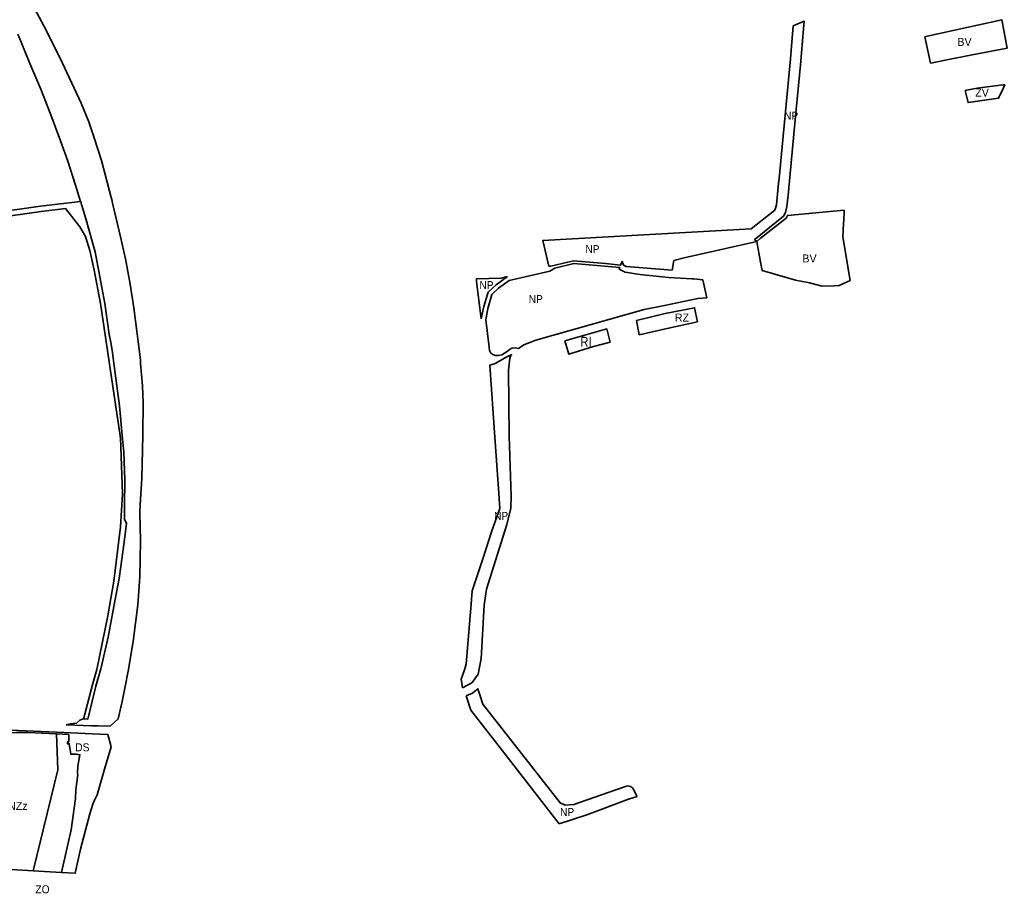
# Model space of a CAD drawing. Extents: x -650971 to -642489, y -1074311 to -1062745.
# Drawn here: x -645155 to -643674, y -1071023 to -1069701 of the extents above; entities that cross this region are included whole.
import ezdxf

# ---------------------------------------------------------------- set-up
doc = ezdxf.new("R2010")
doc.units = 0
doc.header["$LTSCALE"] = 4.8
for name, color, linetype, lineweight in [('15', 7, 'Continuous', 35), ('24', 7, 'Continuous', 35), ('3', 7, 'Continuous', 35), ('40', 7, 'Continuous', 35), ('42', 7, 'Continuous', 35), ('46', 7, 'Continuous', 35), ('48', 7, 'Continuous', 35), ('5', 7, 'Continuous', 35), ('6', 7, 'Continuous', 35), ('62', 7, 'Continuous', 35)]:
    doc.layers.add(name, color=color, linetype=linetype, lineweight=lineweight)

msp = doc.modelspace()

# ---------------------------------------------------------------- linework, layer by layer
at = {"layer": '15'}
for points in [[(-645469.701, -1069990.011), (-645453.852, -1069992.968), (-645350.784, -1070005.227), (-645222.809, -1069993.701), (-645195.011, -1069990.48), (-645124.233, -1069980.695), (-645064.052, -1069973.429)], [(-645064.052, -1069973.429), (-645063.96, -1069973.73), (-645063.23, -1069976.2), (-645062.57, -1069978.46), (-645061.76, -1069981.21), (-645054.73, -1070004.56), (-645047.28, -1070031.83), (-645042.27, -1070049.23), (-645032.21, -1070102.73), (-645027.49, -1070126.56), (-645021.14, -1070173.07), (-645018.56, -1070184.92), (-645016.92, -1070196.32), (-645013.77, -1070220.04), (-645005.98, -1070280.14), (-645001.81, -1070324.58), (-644999.47, -1070349.63), (-644997.87, -1070391.16), (-644998.25, -1070430.5), (-644998.17, -1070450.59), (-644995.14, -1070455.72), (-644998.92, -1070484.58), (-645006.44, -1070538.78), (-645014.07, -1070580.72), (-645022.64, -1070626.93), (-645033.53, -1070674.55), (-645041, -1070700.44), (-645046.63, -1070722.77), (-645053.21, -1070749.75), (-645059.403, -1070749.195)], [(-645004.791, -1070324.889), (-645034.122, -1070126.616), (-645043.92, -1070076.344), (-645050.293, -1070047.035), (-645056.555, -1070026.163), (-645065.235, -1070011.695), (-645086.484, -1069984.195), (-645123.206, -1069988.629), (-645194.003, -1069998.417), (-645221.99, -1070001.66), (-645350.591, -1070013.242), (-645455.073, -1070009.111), (-645454.881, -1070137.836), (-645466.862, -1070133.219), (-645499.142, -1070133.293)], [(-645059.403, -1070749.195), (-645059.308, -1070747.712), (-645045.493, -1070696.321), (-645039.574, -1070675.065), (-645023.048, -1070595.033), (-645014.277, -1070543.11), (-645004.327, -1070461.264), (-645001.312, -1070412.099), (-645004.434, -1070327.302), (-645004.523, -1070326.697), (-645004.791, -1070324.889)]]:
    msp.add_lwpolyline(points, dxfattribs=at)
at = {"layer": '24'}
for points in [[(-645166.67, -1069629), (-645153.33, -1069649.24), (-645150.3, -1069653.84), (-645148.8, -1069656.1), (-645143.56, -1069664.05), (-645118.98, -1069710.08), (-645095.1, -1069757.62), (-645063.26, -1069825.99), (-645051.78, -1069854.2), (-645043.5, -1069878.37), (-645032.85, -1069912.07), (-645024.45, -1069944.43), (-645018.28, -1069967.49)], [(-645064.052, -1069973.429), (-645071.53, -1069948.89), (-645083.31, -1069913.37), (-645094.42, -1069882.65), (-645108.74, -1069843.58), (-645123.84, -1069805.38), (-645140.27, -1069766.68), (-645153.44, -1069734.71), (-645158.43, -1069722.61)], [(-645059.403, -1070749.195), (-645053.21, -1070749.75), (-645046.63, -1070722.77), (-645041, -1070700.44), (-645033.53, -1070674.55), (-645022.64, -1070626.93), (-645014.07, -1070580.72), (-645006.44, -1070538.78), (-644998.92, -1070484.58), (-644995.14, -1070455.72), (-644998.17, -1070450.59), (-644998.25, -1070430.5), (-644997.87, -1070391.16), (-644999.47, -1070349.63), (-645001.81, -1070324.58), (-645005.98, -1070280.14), (-645013.77, -1070220.04), (-645016.92, -1070196.32), (-645018.56, -1070184.92), (-645021.14, -1070173.07), (-645027.49, -1070126.56), (-645032.21, -1070102.73), (-645042.27, -1070049.23), (-645047.28, -1070031.83), (-645054.73, -1070004.56), (-645061.76, -1069981.21), (-645062.57, -1069978.46), (-645063.23, -1069976.2), (-645063.96, -1069973.73), (-645064.052, -1069973.429)], [(-645018.28, -1069967.49), (-645017.46, -1069970.61), (-645016.01, -1069976.23), (-645015.548, -1069978.177)], [(-645015.548, -1069978.177), (-645010.54, -1069999.3), (-645004.02, -1070026.44), (-644996.88, -1070059.73), (-644989.62, -1070097.79), (-644984.21, -1070132.81), (-644979.57, -1070167.9), (-644978.49, -1070180.05), (-644976.94, -1070191.41), (-644974.49, -1070210.98), (-644974.29, -1070213.17), (-644974, -1070216.2), (-644971.47, -1070250.14), (-644970.36, -1070275.49), (-644970.55, -1070321.56), (-644970.61, -1070323.44)], [(-644970.61, -1070323.44), (-644971.37, -1070345.98), (-644972.48, -1070389.15), (-644974.69, -1070427.86), (-644975.29, -1070440.14), (-644974.44, -1070482.48), (-644975.05, -1070536.16), (-644978.44, -1070578.56), (-644985.04, -1070633.43), (-644992.6, -1070677.92), (-644997.14, -1070700.88), (-645001.71, -1070723.39), (-645007.68, -1070749.5), (-645019.57, -1070760.07)], [(-645085.58, -1070758.04), (-645079.38, -1070756.91), (-645070.3, -1070755.92), (-645065.17, -1070751.39), (-645060.46, -1070749.1), (-645059.403, -1070749.195)], [(-645400.05, -1070819.84), (-645385.99, -1070810.35), (-645342.94, -1070779.31), (-645333.12, -1070773.33), (-645321.9, -1070768.47), (-645309.78, -1070764.88), (-645296.51, -1070762.52), (-645275.8, -1070762.66), (-645179.18, -1070765.86), (-645156.988, -1070766.884), (-645100.32, -1070769.5), (-645046.46, -1070771.98), (-645023.25, -1070772.62)], [(-645019.57, -1070760.07), (-645038.44, -1070759.83), (-645047.39, -1070759.71), (-645085.58, -1070758.04)], [(-645100.268, -1070771.946), (-645143, -1070770), (-645161, -1070770), (-645182, -1070771), (-645303, -1070774)], [(-645092.67, -1070979.52), (-645078.23, -1070915.65), (-645071.77, -1070868.73), (-645071.18, -1070855.63), (-645068.07, -1070832.72), (-645068.52, -1070830.52), (-645068.07, -1070820.37), (-645065.01, -1070803.22), (-645070.2, -1070802.33), (-645078.85, -1070802.46), (-645081.13, -1070786.56), (-645083.49, -1070786.92), (-645083.95, -1070783.89), (-645081.57, -1070783.53), (-645081.85, -1070781.59), (-645081.75, -1070772.79), (-645100.268, -1070771.946)], [(-645023.25, -1070772.62), (-645018.18, -1070791.34), (-645028.25, -1070824.83), (-645039.25, -1070863.33), (-645043, -1070871.35), (-645045.74, -1070877.19), (-645050.47, -1070891.48), (-645064.39, -1070944.7), (-645071.99, -1070980.72), (-645092.67, -1070979.52)]]:
    msp.add_lwpolyline(points, dxfattribs=at)
at = {"layer": '3'}
msp.add_line((-643797.75, -1069726.51), (-643791.88, -1069725.25), dxfattribs=at)
for points in [[(-643791.88, -1069725.25), (-643682.61, -1069701.16), (-643674.3, -1069743.53)], [(-643674.3, -1069743.53), (-643729.34, -1069754.3), (-643764.94, -1069761.27), (-643786.35, -1069765.46), (-643789.3, -1069766.05), (-643797.75, -1069726.51)], [(-644050.12, -1070033.64), (-644044.7, -1070029.04), (-644005.92, -1069998.62), (-644004.06, -1069994.59), (-643918.88, -1069986.82)], [(-643918.88, -1069986.82), (-643918.69, -1069992.23), (-643920.16, -1070015.69), (-643920.29, -1070017.73), (-643920.84, -1070026.46), (-643909.87, -1070091.95)], [(-643991.99, -1070091.37), (-644003.7, -1070088.06), (-644022.77, -1070082.66), (-644041.71, -1070077.29), (-644044.18, -1070064.43), (-644050.12, -1070033.64)], [(-643909.87, -1070091.95), (-643926.33, -1070099.5), (-643933.96, -1070100.18), (-643951.99, -1070100.35), (-643971.03, -1070095.79), (-643991.99, -1070091.37)]]:
    msp.add_lwpolyline(points, dxfattribs=at)
at = {"layer": '40'}
for points in [[(-643719.42, -1069803.49), (-643680.83, -1069798.86), (-643678.02, -1069798.52), (-643680.15, -1069803.22), (-643687.2, -1069818.8), (-643733.02, -1069825.4), (-643737.47, -1069807.24)], [(-643737.47, -1069807.24), (-643735.51, -1069806.83), (-643719.42, -1069803.49)]]:
    msp.add_lwpolyline(points, dxfattribs=at)
at = {"layer": '42'}
for points in [[(-645134.973, -1070977.077), (-645098.438, -1070825.558), (-645100.268, -1070771.946)], [(-645100.268, -1070771.946), (-645081.75, -1070772.79), (-645081.85, -1070781.59), (-645081.57, -1070783.53), (-645083.95, -1070783.89), (-645083.49, -1070786.92), (-645081.13, -1070786.56), (-645078.85, -1070802.46), (-645070.2, -1070802.33), (-645065.01, -1070803.22), (-645068.07, -1070820.37), (-645068.52, -1070830.52), (-645068.07, -1070832.72), (-645071.18, -1070855.63), (-645071.77, -1070868.73), (-645078.23, -1070915.65), (-645092.67, -1070979.52), (-645134.973, -1070977.077)]]:
    msp.add_lwpolyline(points, dxfattribs=at)
at = {"layer": '46'}
for points in [[(-645303, -1070774), (-645182, -1070771), (-645161, -1070770), (-645143, -1070770), (-645100.268, -1070771.946)], [(-645100.268, -1070771.946), (-645098.438, -1070825.558), (-645134.973, -1070977.077)], [(-645134.973, -1070977.077), (-645167.47, -1070975.2), (-645178.73, -1070972.35), (-645179.87, -1071004.67), (-645180.506, -1071022.777)]]:
    msp.add_lwpolyline(points, dxfattribs=at)
at = {"layer": '48'}
for points in [[(-644361.74, -1070070.32), (-644370.87, -1070032.13), (-644219.33, -1070023.53), (-644058.55, -1070014.4), (-644022.99, -1069986.58), (-644022.43, -1069984.87), (-644020.26, -1069978.38), (-644017.15, -1069945.93), (-644016.47, -1069938.99), (-644001.29, -1069780.7), (-644000.79, -1069775.42), (-643999.94, -1069765.62), (-643995.17, -1069710.42)], [(-643995.17, -1069710.42), (-643978.85, -1069703.4), (-643984.44, -1069768.58), (-643992.27, -1069851.31), (-644000.52, -1069937.19), (-644003.06, -1069964.06), (-644005.06, -1069981.28), (-644006.96, -1069990.34), (-644009.95, -1069995.74), (-644051.913, -1070029.549), (-644053.18, -1070030.57), (-644050.12, -1070033.64)], [(-644050.12, -1070033.64), (-644159.02, -1070057.84), (-644174.12, -1070062.16), (-644177.01, -1070076.69)], [(-644407.55, -1070194.16), (-644412.54, -1070193.18), (-644416.67, -1070193.7), (-644419.51, -1070194.76), (-644421.88, -1070196.28), (-644424.14, -1070198.29), (-644432.53, -1070203.32), (-644438, -1070204.57), (-644441.8, -1070204.26), (-644445.9, -1070202.83), (-644448.76, -1070200.77), (-644450.72, -1070196.97), (-644451.37, -1070192.02), (-644456.41, -1070151.18), (-644453.22, -1070133.99), (-644447.13, -1070113.11), (-644437.34, -1070103.76), (-644421.26, -1070091.99), (-644360.41, -1070077.91), (-644352.71, -1070073.46), (-644324.42, -1070066.48), (-644255.52, -1070072.5), (-644256.54, -1070075.02), (-644247.3, -1070079.69), (-644225.13, -1070082.95), (-644191.26, -1070086.47), (-644181.81, -1070087.51), (-644147.25, -1070089.35), (-644144.13, -1070089.47), (-644130.91, -1070091.1), (-644125, -1070117.83)], [(-644177.01, -1070076.69), (-644245.9, -1070071.26), (-644249.99, -1070068.9), (-644251.9, -1070063.55), (-644254.13, -1070069.08), (-644276.85, -1070066.62), (-644324.72, -1070062.44), (-644359.02, -1070070.67), (-644361.74, -1070070.32)], [(-644463.28, -1070149.42), (-644470.55, -1070093.61), (-644470.17, -1070089.43), (-644433.19, -1070088.37), (-644423.99, -1070086.17)], [(-644423.99, -1070086.17), (-644440.64, -1070098.4), (-644452.65, -1070109.46), (-644459.09, -1070131.08), (-644463.28, -1070149.42)], [(-644125, -1070117.83), (-644138.24, -1070119.29), (-644140.72, -1070119.57), (-644188.44, -1070129.43)], [(-644188.44, -1070129.43), (-644218.65, -1070135.75), (-644381.21, -1070181.71), (-644399.15, -1070188.55), (-644407.55, -1070194.16)], [(-644450.15, -1070219.06), (-644445.11, -1070217.43), (-644442.2, -1070216.72), (-644423.66, -1070205.86), (-644421.47, -1070204.77), (-644417.36, -1070203.24), (-644418.61, -1070204.51), (-644420.14, -1070208.56), (-644422.5, -1070226.42), (-644421.45, -1070325.29)], [(-644491.42, -1070702.64), (-644493.5, -1070689.75), (-644491.82, -1070685.92), (-644488.01, -1070674.2), (-644485.64, -1070666.7), (-644479.06, -1070583.13), (-644476.94, -1070557.45), (-644464.98, -1070521.13), (-644460.5, -1070507.68), (-644447.14, -1070467.28), (-644435.51, -1070433.85), (-644437.53, -1070404.1), (-644440.36, -1070362.62), (-644445.28, -1070290.84), (-644450.15, -1070219.06)], [(-644421.45, -1070325.29), (-644418.23, -1070415.62), (-644418.69, -1070433.36), (-644424.87, -1070457.83), (-644455.2, -1070554.88)], [(-644455.2, -1070554.88), (-644458.85, -1070579.04), (-644463.28, -1070659.06), (-644467.84, -1070682.37)], [(-644467.84, -1070682.37), (-644475.49, -1070692.64), (-644477.46, -1070695.09), (-644491.42, -1070702.64)], [(-644485.61, -1070714.95), (-644476.35, -1070710.99), (-644468.1, -1070704.23), (-644465.31, -1070713.25)], [(-644346.21, -1070906.61), (-644424.37, -1070806.03), (-644478.67, -1070736.28), (-644485.61, -1070714.95)], [(-644465.31, -1070713.25), (-644460.82, -1070727.21), (-644344.86, -1070875.09), (-644337.15, -1070878.64), (-644324.34, -1070877.71), (-644282.77, -1070863.19), (-644246.93, -1070850.52), (-644243.15, -1070849.89), (-644239.47, -1070850.71), (-644236.3, -1070852.87), (-644234.66, -1070855.08), (-644229.12, -1070865.52)], [(-644229.12, -1070865.52), (-644242.29, -1070869.82), (-644305.07, -1070893.39), (-644346.21, -1070906.61)]]:
    msp.add_lwpolyline(points, dxfattribs=at)
at = {"layer": '5'}
for points in [[(-644338.06, -1070182.64), (-644275.05, -1070164.59), (-644269.84, -1070184.57)], [(-644269.84, -1070184.57), (-644295.01, -1070190.9), (-644331.9, -1070202.4), (-644338.06, -1070182.64)]]:
    msp.add_lwpolyline(points, dxfattribs=at)
at = {"layer": '6'}
for points in [[(-644230.4, -1070152.08), (-644187.11, -1070141.58), (-644143.31, -1070132.95), (-644138.78, -1070154.07)], [(-644138.78, -1070154.07), (-644182.31, -1070163.66), (-644226.23, -1070173.28), (-644230.4, -1070152.08)]]:
    msp.add_lwpolyline(points, dxfattribs=at)

# ---------------------------------------------------------------- texts
at = {"layer": '62'}
for s, p in [('BV', (-643749.135, -1069740.303)), ('ZV', (-643722.385, -1069816.315)), ('BV', (-643981.639, -1070065.037)), ('RZ', (-644172.882, -1070153.612)), ('NZz', (-645172.866, -1070885.823))]:
    msp.add_text(s, height=12, dxfattribs=at).set_placement(p)
for s, height, width, p in [('NP', 12, 0.95, (-644008.985, -1069850.967)), ('NP', 12, 0.95, (-644306.985, -1070050.967)), ('NP', 12, 0.95, (-644465.985, -1070104.967)), ('NP', 12, 0.95, (-644391.985, -1070125.967)), ('RI', 15, 0.85, (-644314.705, -1070191.481)), ('NP', 12, 0.95, (-644444, -1070450.967)), ('DS', 12, 0.95, (-645072.003, -1070798.001)), ('NP', 12, 0.95, (-644345, -1070894.967)), ('ZO', 12, 0.95, (-645131.758, -1071010.853))]:
    msp.add_text(s, height=height, dxfattribs=dict(at, width=width)).set_placement(p)

doc.saveas('drawing.dxf')
